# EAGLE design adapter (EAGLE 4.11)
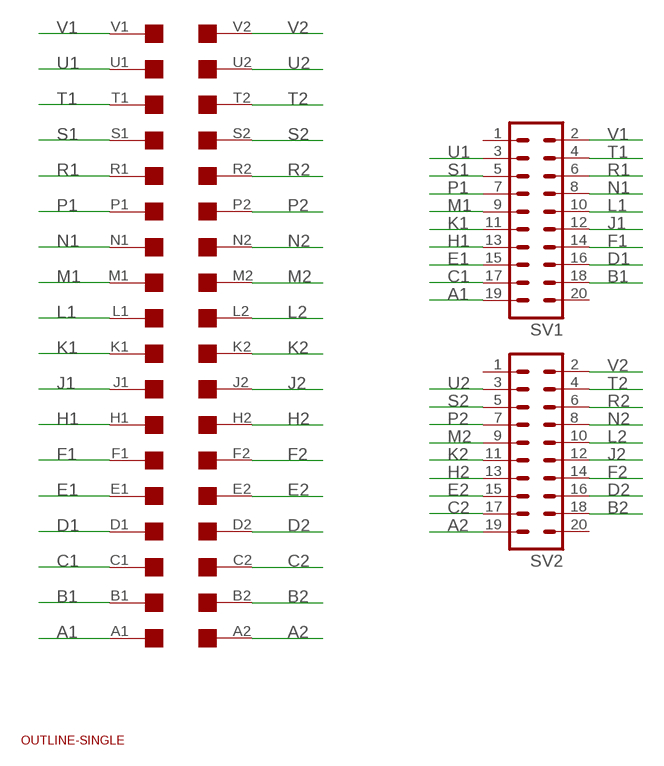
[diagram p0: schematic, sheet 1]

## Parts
SV1  MA10-2W  [MA10-2W]
SV2  MA10-2W  [MA10-2W]
U$1  OUTLINE-SINGLE  [SINGLE]
U$2  SINGLE  [EDGE-CON2]

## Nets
A1: SV1.19 U$2.A1
A2: SV2.19 U$2.A2
B1: SV1.18 U$2.B1
B2: SV2.18 U$2.B2
C1: SV1.17 U$2.C1
C2: SV2.17 U$2.C2
D1: SV1.16 U$2.D1
D2: SV2.16 U$2.D2
E1: SV1.15 U$2.E1
E2: SV2.15 U$2.E2
F1: SV1.14 U$2.F1
F2: SV2.14 U$2.F2
H1: SV1.13 U$2.H1
H2: SV2.13 U$2.H2
J1: SV1.12 U$2.J1
J2: SV2.12 U$2.J2
K1: SV1.11 U$2.K1
K2: SV2.11 U$2.K2
L1: SV1.10 U$2.L1
L2: SV2.10 U$2.L2
M1: SV1.9 U$2.M1
M2: SV2.9 U$2.M2
N1: SV1.8 U$2.N1
N2: SV2.8 U$2.N2
P1: SV1.7 U$2.P1
P2: SV2.7 U$2.P2
R1: SV1.6 U$2.R1
R2: SV2.6 U$2.R2
S1: SV1.5 U$2.S1
S2: SV2.5 U$2.S2
T1: SV1.4 U$2.T1
T2: SV2.4 U$2.T2
U1: SV1.3 U$2.U1
U2: SV2.3 U$2.U2
V1: SV1.2 U$2.V1
V2: SV2.2 U$2.V2
Unconnected: SV1.1 SV1.20 SV2.1 SV2.20

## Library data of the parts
SV1 SV2 = con-lstb:MA10-2W: PIN HEADER
U$1 = dec-con:OUTLINE-*: Board outlines for DEC boards.
U$2 = dec-con:SINGLE: Single-Height DEC board

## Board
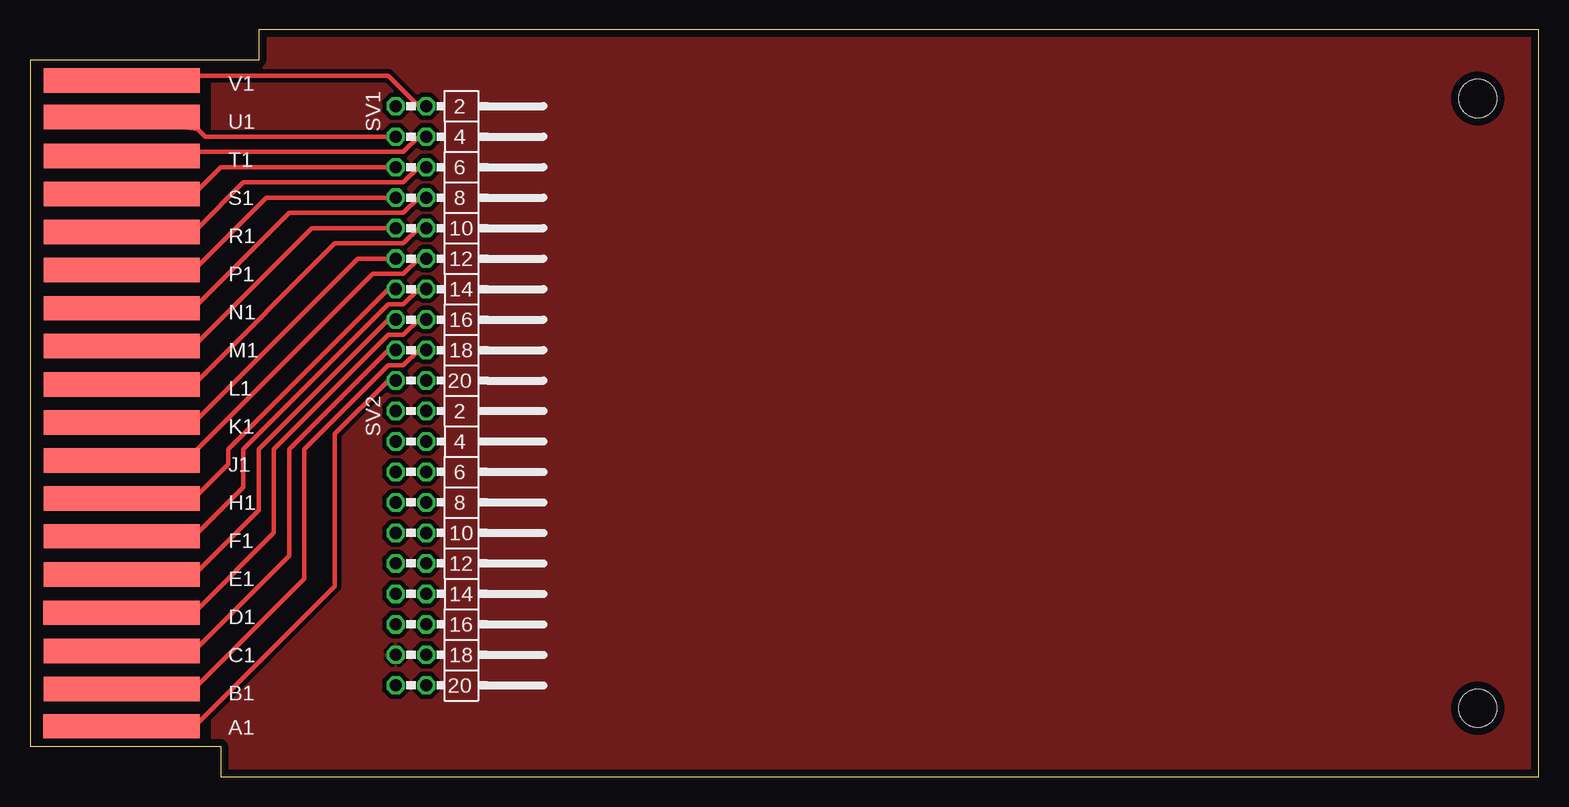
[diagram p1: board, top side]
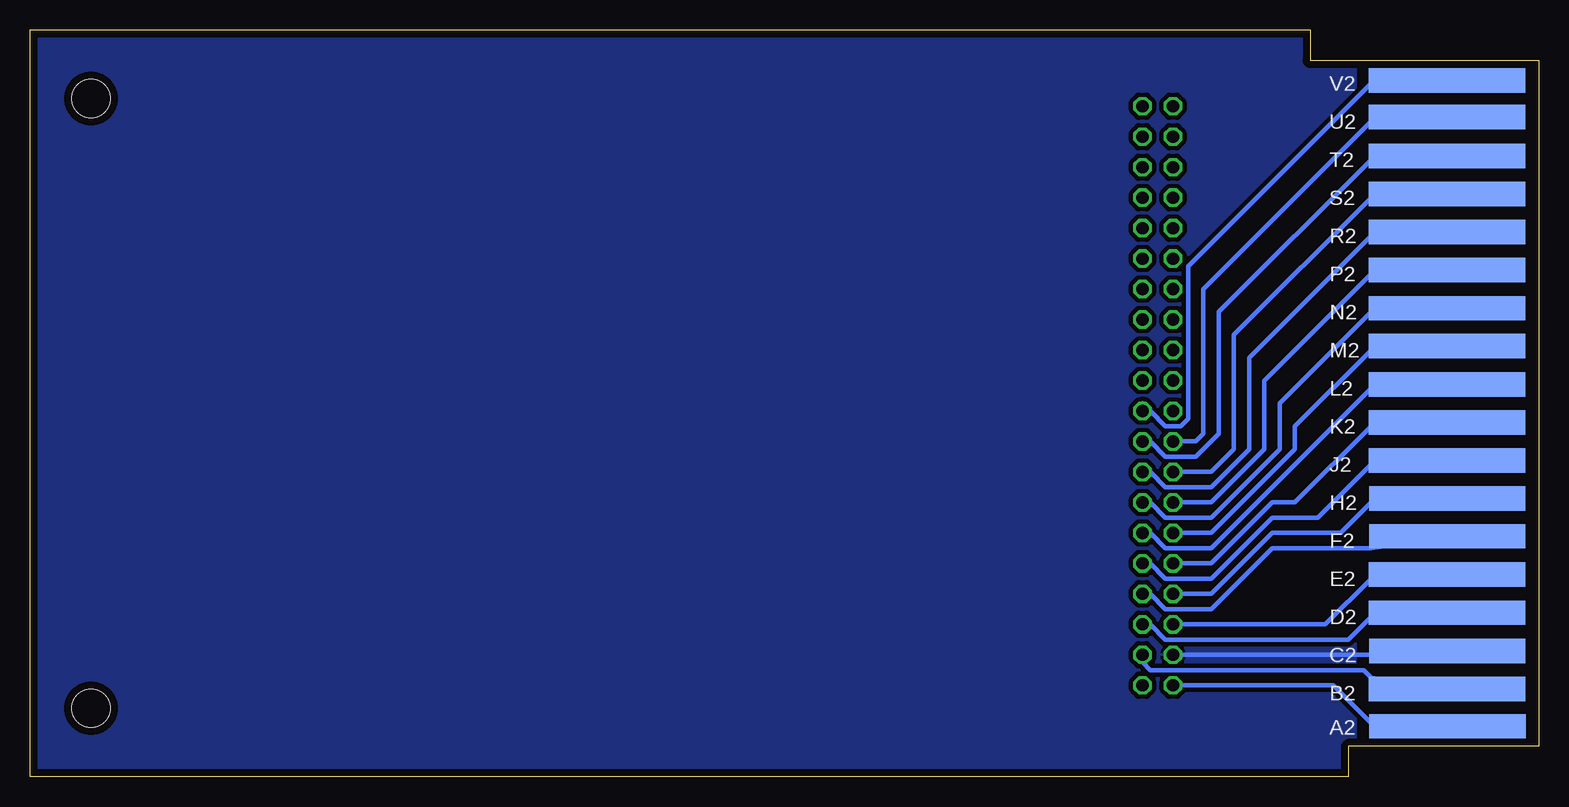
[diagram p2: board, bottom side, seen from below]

Size 125.73 x 62.23 mm. Coordinates in mm from the lower left corner, seen from the top.
Copper layers (1*16): Top 0.035mm / dielectric 1.5mm / Bottom 0.035mm
Design rules "15mils": minimum track width 15mil, minimum drill 24mil, track to track 15mil, track to pad 10mil, pad to pad 10mil, via to via 10mil, smd to smd 10mil, copper to edge 25mil, drill to drill 10mil, minimum pad ring 10mil, minimum via ring 8mil, stop-mask expansion 0mil, vias tented up to drill 0mil, thermal gap 10mil

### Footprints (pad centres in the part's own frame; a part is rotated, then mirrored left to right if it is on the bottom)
MA10-2W = drill 1.016 octagon: 1 -11.43,-1.27; 2 -11.43,1.27; 3 -8.89,-1.27; 4 -8.89,1.27; 5 -6.35,-1.27; 6 -6.35,1.27; 7 -3.81,-1.27; 8 -3.81,1.27; 9 -1.27,-1.27; 10 -1.27,1.27; 11 1.27,-1.27; 12 1.27,1.27; 13 3.81,-1.27; 14 3.81,1.27; 15 6.35,-1.27; 16 6.35,1.27; 17 8.89,-1.27; 18 8.89,1.27; 19 11.43,-1.27; 20 11.43,1.27
SINGLE = hole 3.175: 120.65,56.515; 120.65,5.715
EDGE-CON2 = smd 13.017 x 2.032: A1 7.633,4.207; B1 7.639,7.327; C1 7.636,10.489; D1 7.633,13.665; E1 7.642,16.84; F1 7.642,20.041; H1 7.642,23.19; J1 7.642,26.34; K1 7.642,29.515; L1 7.642,32.69; M1 7.642,35.89; N1 7.642,39.04; P1 7.642,42.24; R1 7.642,45.39; S1 7.642,48.565; T1 7.642,51.74; U1 7.642,54.966; V1 7.642,58.026 | smd 13.017 x 2.032 bottom: A2 7.614,4.207; B2 7.642,7.328; C2 7.617,10.49; D2 7.642,13.665; E2 7.642,16.84; F2 7.617,20.041; H2 7.617,23.19; J2 7.642,26.34; K2 7.642,29.515; L2 7.642,32.69; M2 7.642,35.89; N2 7.642,39.04; P2 7.642,42.24; R2 7.642,45.39; S2 7.642,48.565; T2 7.642,51.74; U2 7.642,54.966; V2 7.642,58.026

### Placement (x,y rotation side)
SV1  31.75,44.45 270 top
SV2  31.75,19.05 270 top
U$1  0,0 0 top
U$2  0,0 0 top

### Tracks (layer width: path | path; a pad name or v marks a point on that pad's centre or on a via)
A1
  Top 0.381: SV1.19 29.85,33.02 25.4,28.57 25.4,15.88 13.97,4.45 U$2.A1
A2
  Bottom 0.381: SV2.19 17.15,7.62 13.97,4.45 U$2.A2
B1
  Top 0.381: SV1.18 32.39,35.56 31.12,34.29 29.85,34.29 22.86,27.3 22.86,16.51 13.97,7.62 U$2.B1
B2
  Bottom 0.381: SV2.18 33.02,9.53 32.39,8.89 14.61,8.89 13.97,8.26 U$2.B2
C1
  Top 0.381: SV1.17 29.85,35.56 21.59,27.3 21.59,18.41 13.97,10.79 U$2.C1
C2
  Bottom 0.381: SV2.17 13.97,10.16 U$2.C2
  pour Bottom (isolate 0.305): 15.24,0 15.24,62.23 125.73,62.23 125.73,0
  pour Top (isolate 0.305): 15.24,0 15.24,62.23 125.73,62.23 125.73,0
D1
  Top 0.381: SV1.16 32.39,38.1 31.12,36.83 29.85,36.83 20.32,27.3 20.32,20.32 13.97,13.97 U$2.D1
D2
  Bottom 0.381: SV2.16 32.39,12.7 31.12,11.43 15.88,11.43 13.97,13.34 U$2.D2
E1
  Top 0.381: SV1.15 29.85,38.1 19.05,27.3 19.05,22.23 13.97,17.14 U$2.E1
E2
  Bottom 0.381: SV2.15 17.78,12.7 13.97,16.51 U$2.E2
F1
  Top 0.381: SV1.14 32.39,40.64 31.12,39.37 29.85,39.37 17.78,27.3 17.78,24.13 13.97,20.32 U$2.F1
F2
  Bottom 0.381: SV2.14 32.39,15.24 31.12,13.97 27.31,13.97 22.23,19.05 13.97,19.05 U$2.F2
H1
  Top 0.381: SV1.13 29.85,40.64 16.51,27.3 16.51,26.04 13.97,23.5 U$2.H1
H2
  Bottom 0.381: SV2.13 27.31,15.24 22.23,20.32 16.51,20.32 13.97,22.86 U$2.H2
J1
  Top 0.381: SV1.12 32.39,43.18 31.12,41.91 28.58,41.91 12.7,26.04 U$2.J1
J2
  Bottom 0.381: SV2.12 32.39,17.78 31.12,16.51 27.31,16.51 22.23,21.59 18.42,21.59 13.97,26.04 U$2.J2
K1
  Top 0.381: SV1.11 27.31,43.18 13.97,29.84 U$2.K1
K2
  Bottom 0.381: SV2.11 27.31,17.78 22.23,22.86 20.32,22.86 13.97,29.21 U$2.K2
L1
  Top 0.381: SV1.10 32.39,45.72 31.12,44.45 25.4,44.45 13.97,33.02 U$2.L1
L2
  Bottom 0.381: SV2.10 32.39,20.32 31.12,19.05 27.31,19.05 13.97,32.38 U$2.L2
M1
  Top 0.381: SV1.9 23.5,45.72 13.97,36.2 U$2.M1
M2
  Bottom 0.381: SV2.9 27.31,20.32 20.32,27.3 20.32,29.21 13.97,35.56 U$2.M2
N1
  Top 0.381: SV1.8 32.39,48.26 31.12,46.99 21.59,46.99 13.97,39.37 U$2.N1
N2
  Bottom 0.381: SV2.8 32.39,22.86 31.12,21.59 27.31,21.59 21.59,27.3 21.59,31.11 13.97,38.73 U$2.N2
P1
  Top 0.381: SV1.7 19.69,48.26 13.97,42.55 U$2.P1
P2
  Bottom 0.381: SV2.7 27.31,22.86 22.86,27.3 22.86,33.02 13.97,41.91 U$2.P2
R1
  Top 0.381: SV1.6 32.39,50.8 31.12,49.53 17.78,49.53 13.97,45.72 U$2.R1
R2
  Bottom 0.381: SV2.6 32.39,25.4 31.12,24.13 27.31,24.13 24.13,27.3 24.13,34.92 13.97,45.09 U$2.R2
S1
  Top 0.381: SV1.5 15.88,50.8 13.97,48.9 U$2.S1
S2
  Bottom 0.381: SV2.5 27.31,25.4 25.4,27.3 25.4,36.83 13.97,48.26 U$2.S2
T1
  Top 0.381: SV1.4 32.39,53.34 31.12,52.07 13.97,52.07 U$2.T1
T2
  Bottom 0.381: SV2.4 32.39,27.94 31.12,26.67 28.58,26.67 26.67,28.57 26.67,38.73 13.97,51.44 U$2.T2
U1
  Top 0.381: SV1.3 14.61,53.34 13.97,53.98 U$2.U1
U2
  Bottom 0.381: SV2.3 28.58,27.94 27.94,28.57 27.94,40.64 13.97,54.61 U$2.U2
V1
  Top 0.381: SV1.2 32.39,55.88 29.85,58.42 13.97,58.42 U$2.V1
V2
  Bottom 0.381: 33.02,31.11 SV2.2 32.39,30.48 31.12,29.21 29.85,29.21 29.21,29.84 29.21,42.55 13.97,57.78 U$2.V2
